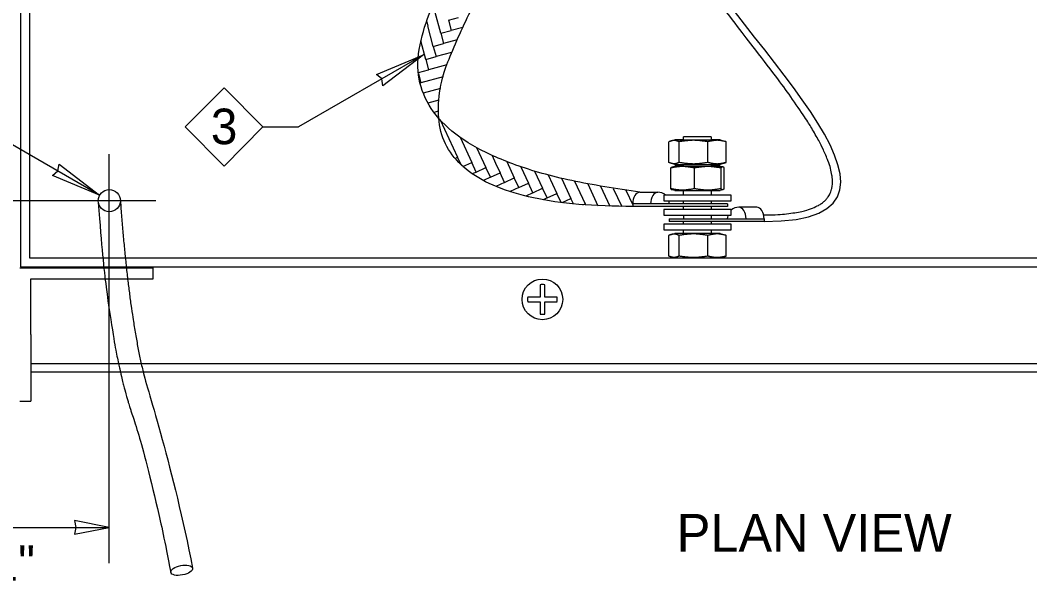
# Model space of a CAD drawing. Extents: x 99862 to 103680, y 99470 to 102076.
# Drawn here: x 101295.5 to 101750, y 101268.9 to 101521 of the extents above; entities that cross this region are included whole.
import ezdxf

# ---------------------------------------------------------------- set-up
doc = ezdxf.new("R2010")
doc.units = 0
for name, color, linetype in [('Level 1', 7, 'Continuous'), ('Level 10', 7, 'Continuous'), ('Level 11', 7, 'Continuous'), ('Level 13', 7, 'Continuous'), ('Level 14', 7, 'Continuous'), ('Level 15', 7, 'Continuous'), ('Level 20', 7, 'Continuous'), ('Level 6', 7, 'Continuous'), ('Level 9', 7, 'Continuous')]:
    doc.layers.add(name, color=color, linetype=linetype)

msp = doc.modelspace()

# ---------------------------------------------------------------- linework, layer by layer
at = {"layer": 'Level 1'}
for p, q in [((101295.71, 101675.72), (101295.71, 101410.08)), ((101299.71, 101675.72), (101299.71, 101414.08)), ((101295.71, 101410.08), (102014.99, 101410.08)), ((101299.71, 101414.08), (102010.99, 101414.08)), ((102010.35, 101366.5), (101300.35, 101366.5)), ((101300.35, 101362.86), (102010.35, 101362.86))]:
    msp.add_line(p, q, dxfattribs=at)
msp.add_circle((101335.63, 101439.83), 5, dxfattribs=at)
at = {"layer": 'Level 10'}
for p, q in [((101587.44, 101457.01), (101587.44, 101466.35)), ((101588.22, 101466.61), (101590.23, 101467.17)), ((101592.13, 101457.01), (101592.13, 101466.35)), ((101594.13, 101467.17), (101594.13, 101468.51)), ((101605.06, 101457.01), (101605.06, 101466.35)), ((101606.63, 101468.51), (101606.63, 101467.17)), ((101610.54, 101467.17), (101612.55, 101466.61)), ((101612.54, 101466.61), (101613.32, 101466.35)), ((101613.32, 101457.01), (101613.32, 101466.35)), ((101590.23, 101456.19), (101588.22, 101456.75)), ((101588.96, 101455.03), (101590.23, 101455.38)), ((101594.13, 101455.38), (101594.13, 101456.19)), ((101606.63, 101456.19), (101606.63, 101455.38)), ((101612.55, 101456.75), (101610.54, 101456.19)), ((101610.54, 101455.38), (101611.8, 101455.03)), ((101612.54, 101456.75), (101613.32, 101457.01)), ((101588.43, 101454.56), (101588.98, 101455.03)), ((101588.43, 101445.23), (101588.43, 101454.56)), ((101599.05, 101445.23), (101599.05, 101454.56)), ((101611, 101445.22), (101611.01, 101454.56)), ((101612.34, 101454.56), (101611.79, 101455.03)), ((101612.34, 101445.22), (101612.34, 101454.56)), ((101588.43, 101445.23), (101588.97, 101444.75)), ((101590.22, 101444.41), (101588.96, 101444.76)), ((101594.13, 101442.33), (101594.13, 101444.41)), ((101606.63, 101444.41), (101606.63, 101442.33)), ((101611.8, 101444.76), (101610.54, 101444.41)), ((101612.34, 101445.22), (101611.79, 101444.75)), ((101594.13, 101438.46), (101594.13, 101439.83)), ((101594.13, 101435.91), (101594.13, 101437.21)), ((101606.63, 101439.83), (101606.63, 101438.46)), ((101606.63, 101437.21), (101606.63, 101435.91)), ((101594.13, 101433.41), (101594.13, 101431.73)), ((101606.63, 101433.41), (101606.63, 101431.73)), ((101594.13, 101429.23), (101594.13, 101430.48)), ((101606.63, 101430.48), (101606.63, 101429.23)), ((101587.44, 101414.91), (101587.44, 101424.24)), ((101588.22, 101424.5), (101590.22, 101425.06)), ((101592.12, 101414.9), (101592.12, 101424.24)), ((101594.13, 101425.06), (101594.13, 101426.73)), ((101605.06, 101414.9), (101605.06, 101424.24)), ((101606.63, 101426.73), (101606.63, 101425.06)), ((101610.54, 101425.06), (101612.55, 101424.5)), ((101612.53, 101424.5), (101613.32, 101424.24)), ((101613.32, 101414.9), (101613.32, 101424.24)), ((101590.22, 101414.09), (101588.22, 101414.64)), ((101612.55, 101414.65), (101610.54, 101414.08)), ((101612.53, 101414.64), (101613.32, 101414.9)), ((101529.56, 101402.06), (101529.56, 101396.49)), ((101531.62, 101396.49), (101531.62, 101402.06)), ((101529.56, 101396.49), (101523.99, 101396.49)), ((101537.19, 101396.49), (101531.62, 101396.49)), ((101523.99, 101394.42), (101529.56, 101394.42)), ((101529.56, 101394.42), (101529.56, 101388.86)), ((101531.62, 101388.86), (101531.62, 101394.42)), ((101531.62, 101394.42), (101537.19, 101394.42))]:
    msp.add_line(p, q, dxfattribs=at)
msp.add_circle((101530.59, 101395.46), 9.15, dxfattribs=at)
for centre, start, end in [((101530.59, 101393.46), 83.1584, 96.8416), ((101532.59, 101395.46), 173.1584, 186.8416), ((101528.59, 101395.46), 353.1584, 6.8416), ((101530.59, 101397.46), 263.1584, 276.8416)]:
    msp.add_arc(centre, 8.66, start, end, dxfattribs=at)
for centre, major_axis, start_param, end_param in [((101600.38, 101467.17), (10.16, 0), 2.233649, 3.141532), ((101600.38, 101467.17), (10.16, 0), 3.141532, 5.077835), ((101600.38, 101468.51), (-6.25, 0), 3.141588, 6.283185), ((101600.38, 101467.17), (-6.25, 0), 6.263057, 6.283185), ((101600.38, 101467.17), (-6.25, 0), 0, 3.141593), ((101600.38, 101467.17), (10.16, 0), 5.077835, 6.283246), ((101600.38, 101467.17), (10.16, 0), 0.00006, 0.907905), ((101600.38, 101467.17), (-6.25, 0), 3.141593, 3.160019), ((101600.38, 101456.19), (10.16, 0), 3.141653, 5.077835), ((101600.38, 101455.38), (10.16, 0), 2.233603, 3.141532), ((101600.38, 101455.38), (10.16, 0), 3.141532, 5.657889), ((101600.38, 101456.19), (-6.25, 0), 6.276167, 6.283185), ((101600.38, 101455.38), (-6.25, 0), 6.270079, 6.283185), ((101600.38, 101455.38), (-6.25, 0), 6.283185, 9.424778), ((101600.38, 101456.19), (10.16, 0), 5.077835, 6.283125), ((101600.38, 101455.38), (10.16, 0), 0.00006, 0.907855), ((101600.38, 101455.38), (10.16, 0), 5.657889, 6.283246), ((101600.38, 101444.41), (10.16, 0), 3.141653, 5.657889), ((101600.38, 101444.41), (-6.25, 0), 6.270079, 6.283185), ((101600.38, 101444.41), (10.16, 0), 5.657889, 6.283125), ((101600.38, 101425.06), (10.16, 0), 0.00006, 3.141524)]:
    msp.add_ellipse(centre, major_axis=major_axis, ratio=0.000017, start_param=start_param, end_param=end_param, dxfattribs=at)
for points in [[(101588.23, 101466.62), (101587.97, 101466.53), (101587.71, 101466.44), (101587.44, 101466.35)], [(101592.13, 101466.35), (101590.83, 101466.87), (101589.53, 101467.02), (101588.23, 101466.62)], [(101605.06, 101466.35), (101600.75, 101467.02), (101596.44, 101467.01), (101592.13, 101466.35)], [(101613.32, 101466.35), (101610.57, 101467.02), (101607.82, 101467), (101605.06, 101466.35)], [(101588.23, 101456.75), (101587.97, 101456.84), (101587.71, 101456.93), (101587.44, 101457.01)], [(101592.13, 101457.01), (101590.83, 101456.5), (101589.53, 101456.34), (101588.23, 101456.75)], [(101599.05, 101454.56), (101595.53, 101455.18), (101591.95, 101455.25), (101588.43, 101454.56)], [(101605.06, 101457.01), (101600.75, 101456.34), (101596.44, 101456.36), (101592.13, 101457.01)], [(101611.01, 101454.56), (101607.02, 101455.23), (101603.04, 101455.22), (101599.05, 101454.56)], [(101613.32, 101457.01), (101610.57, 101456.34), (101607.82, 101456.36), (101605.06, 101457.01)], [(101611.79, 101455.03), (101611.53, 101455.14), (101611.27, 101454.85), (101611.01, 101454.56)], [(101599.05, 101445.23), (101595.53, 101444.6), (101591.95, 101444.53), (101588.43, 101445.23)], [(101611, 101445.22), (101607.02, 101444.55), (101603.04, 101444.57), (101599.05, 101445.23)], [(101611.79, 101444.75), (101611.53, 101444.65), (101611.27, 101444.94), (101611, 101445.22)], [(101588.23, 101424.51), (101587.97, 101424.42), (101587.7, 101424.33), (101587.44, 101424.24)], [(101592.12, 101424.24), (101590.83, 101424.76), (101589.53, 101424.91), (101588.23, 101424.51)], [(101605.06, 101424.24), (101600.75, 101424.91), (101596.44, 101424.9), (101592.12, 101424.24)], [(101613.32, 101424.24), (101610.57, 101424.91), (101607.82, 101424.9), (101605.06, 101424.24)], [(101588.23, 101414.64), (101587.97, 101414.73), (101587.7, 101414.82), (101587.44, 101414.91)], [(101592.12, 101414.9), (101590.83, 101414.39), (101589.53, 101414.23), (101588.23, 101414.64)], [(101605.06, 101414.9), (101600.75, 101414.23), (101596.44, 101414.25), (101592.12, 101414.9)], [(101613.32, 101414.9), (101610.57, 101414.23), (101607.82, 101414.25), (101605.06, 101414.9)]]:
    msp.add_open_spline(points, degree=2, dxfattribs=at)
at = {"layer": 'Level 11'}
for p, q in [((101484.87, 101515.16), (101482.39, 101524.43)), ((101478.5, 101520.38), (101478.99, 101518.55)), ((101488.27, 101521.04), (101492.9, 101522.28)), ((101488.27, 101521.04), (101489.51, 101516.4)), ((101481.48, 101509.28), (101478.99, 101518.55)), ((101484.87, 101515.16), (101489.51, 101516.4)), ((101484.87, 101515.16), (101486.11, 101510.52)), ((101494.76, 101517.81), (101489.51, 101516.4)), ((101478.08, 101503.4), (101475.83, 101511.8)), ((101481.48, 101509.28), (101486.11, 101510.52)), ((101492.19, 101512.15), (101486.11, 101510.52)), ((101481.48, 101509.28), (101482.72, 101504.64)), ((101489.73, 101506.52), (101482.72, 101504.64)), ((101478.08, 101503.4), (101482.72, 101504.64)), ((101478.08, 101503.4), (101479.32, 101498.77)), ((101487.61, 101500.99), (101479.32, 101498.77)), ((101474.75, 101497.54), (101479.33, 101498.77)), ((101474.79, 101497.13), (101475.93, 101492.89)), ((101475.54, 101492.78), (101475.93, 101492.89)), ((101485.89, 101495.55), (101475.93, 101492.89)), ((101484.65, 101490.25), (101476.98, 101488.2)), ((101483.91, 101485.09), (101479.06, 101483.79)), ((101483.7, 101480.06), (101481.8, 101479.55)), ((101484.59, 101476.19), (101492.42, 101459.4)), ((101493.53, 101468.37), (101498.8, 101457.07)), ((101500.99, 101463.72), (101505.18, 101454.75)), ((101507.91, 101460.25), (101509.53, 101456.78)), ((101491.29, 101458.87), (101492.42, 101459.4)), ((101494.02, 101455.97), (101492.42, 101459.4)), ((101494.83, 101455.22), (101498.8, 101457.07)), ((101500.83, 101452.72), (101498.8, 101457.07)), ((101509.53, 101456.78), (101511.55, 101452.43)), ((101514.51, 101457.46), (101517.93, 101450.11)), ((101520.88, 101455.15), (101524.31, 101447.79)), ((101500.83, 101452.72), (101499.06, 101451.9)), ((101500.83, 101452.72), (101505.18, 101454.75)), ((101507.2, 101450.4), (101505.18, 101454.75)), ((101507.2, 101450.4), (101511.55, 101452.43)), ((101513.58, 101448.08), (101511.55, 101452.43)), ((101527.1, 101453.16), (101530.69, 101445.47)), ((101533.19, 101451.47), (101537.07, 101443.14)), ((101507.2, 101450.4), (101504.01, 101448.91)), ((101507.2, 101450.4), (101507.2, 101450.4)), ((101513.58, 101448.08), (101509.66, 101446.25)), ((101513.58, 101448.08), (101517.93, 101450.11)), ((101519.96, 101445.76), (101517.93, 101450.11)), ((101519.96, 101445.76), (101524.31, 101447.79)), ((101526.34, 101443.44), (101524.31, 101447.79)), ((101539.19, 101449.95), (101543.45, 101440.82)), ((101545.11, 101448.61), (101549.83, 101438.5)), ((101550.97, 101447.4), (101555.54, 101437.6)), ((101556.76, 101446.34), (101560.94, 101437.37)), ((101519.96, 101445.76), (101516.01, 101443.92)), ((101526.34, 101443.44), (101523.1, 101441.93)), ((101526.34, 101443.44), (101530.69, 101445.47)), ((101532.72, 101441.12), (101530.69, 101445.47)), ((101532.72, 101441.12), (101537.07, 101443.14)), ((101538.98, 101439.05), (101537.07, 101443.14)), ((101562.5, 101445.39), (101566.3, 101437.25)), ((101568.2, 101444.53), (101571.25, 101437.99)), ((101532.72, 101441.12), (101530.93, 101440.28)), ((101539.51, 101438.99), (101543.45, 101440.82)), ((101544.57, 101438.43), (101543.45, 101440.82)), ((101548.85, 101438.04), (101549.83, 101438.5)), ((101550.08, 101437.95), (101549.83, 101438.5))]:
    msp.add_line(p, q, dxfattribs=at)
for points in [[(101574.51, 101443.65), (101428.47, 101462.51), (101563.15, 101636.34), (101684.52, 101785.6), (101556.08, 101806.12), (101516.64, 101714.68), (101504.48, 101712.39)], [(101571.25, 101437.21), (101460.29, 101437.21), (101519.62, 101576.95), (101643.97, 101690.88), (101661.74, 101764.81), (101582.83, 101796.17), (101529.92, 101740.64), (101501.22, 101722.24)]]:
    msp.add_open_spline(points, degree=2, dxfattribs=at)
at = {"layer": 'Level 13'}
for p, q in [((101574.51, 101443.65), (101582.57, 101443.65)), ((101571.25, 101438.46), (101571.25, 101437.21)), ((101613.87, 101438.46), (101571.25, 101438.46)), ((101613.87, 101437.21), (101571.25, 101437.21)), ((101613.87, 101438.46), (101613.87, 101437.21)), ((101627.09, 101436.91), (101619.02, 101436.91)), ((101587.73, 101431.73), (101587.73, 101430.48)), ((101587.73, 101431.73), (101630.35, 101431.73)), ((101630.35, 101430.48), (101587.73, 101430.48)), ((101630.35, 101431.73), (101630.35, 101430.48))]:
    msp.add_line(p, q, dxfattribs=at)
for points in [[(101585.28, 101439.83), (101615.49, 101439.83), (101615.49, 101442.33), (101585.28, 101442.33)], [(101585.28, 101433.41), (101615.49, 101433.41), (101615.49, 101435.91), (101585.28, 101435.91)], [(101585.27, 101426.73), (101615.49, 101426.73), (101615.49, 101429.23), (101585.27, 101429.23)]]:
    msp.add_lwpolyline(points, close=True, dxfattribs=at)
for centre, start, end in [((101582.57, 101438.46), 48.2543, 90.0019), ((101582.57, 101438.46), 0.0024, 15.3086), ((101619.02, 101431.73), 89.9981, 131.7457), ((101619.02, 101431.73), 164.6914, 179.9976)]:
    msp.add_arc(centre, 5.19, start, end, dxfattribs=at)
for centre, major_axis, ratio, start_param, end_param in [((101574.51, 101438.46), (0, 5.19), 0.628956, 6.283185, 7.853993), ((101582.57, 101438.46), (0, -5.19), 0.628956, 3.141593, 4.7124), ((101600.38, 101442.33), (-6.4, 0), 0.000017, 3.141593, 3.359984), ((101619.02, 101431.73), (0, -5.19), 0.628956, 1.570785, 3.141593), ((101627.09, 101431.73), (0, 5.19), 0.628956, 4.712377, 6.283185)]:
    msp.add_ellipse(centre, major_axis=major_axis, ratio=ratio, start_param=start_param, end_param=end_param, dxfattribs=at)
at = {"layer": 'Level 14'}
msp.add_ellipse((101368.2, 101273.59), major_axis=(4.9, 0.94), ratio=0.429494, dxfattribs=at)
for points, degree in [([(101330.68, 101439.11), (101332.16, 101418.41), (101334.1, 101400.31), (101337.72, 101376.97), (101339.05, 101369.82), (101340.55, 101363.15), (101340.58, 101363.01), (101340.61, 101362.87)], 3), ([(101340.63, 101439.83), (101344.08, 101391.56), (101350.84, 101362.89)], 2), ([(101340.61, 101362.87), (101341.31, 101359.76), (101342.05, 101356.79), (101343.21, 101352.48), (101343.62, 101351.03), (101344.25, 101348.93), (101344.57, 101347.89), (101344.94, 101346.7), (101345.13, 101346.11), (101345.23, 101345.81), (101345.27, 101345.69), (101345.3, 101345.61), (101345.31, 101345.56), (101348.49, 101335.92), (101351.58, 101325.03), (101357.58, 101300.73), (101360.49, 101287.31), (101363.3, 101272.65)], 3), ([(101350.85, 101362.88), (101352.7, 101355.02), (101364.57, 101318.96), (101373.1, 101274.53)], 3)]:
    msp.add_open_spline(points, degree=degree, dxfattribs=at)
at = {"layer": 'Level 15'}
for p, q in [((101477.12, 101505.5), (101420.82, 101473)), ((101331.3, 101442.33), (101223.04, 101504.83)), ((101404.82, 101473), (101420.82, 101473)), ((101335.63, 101276.86), (101335.63, 101460.83)), ((101356.63, 101439.83), (101162.49, 101439.83)), ((101248.49, 101292.86), (101335.63, 101292.86))]:
    msp.add_line(p, q, dxfattribs=at)
for points in [[(101477.12, 101505.5), (101458.84, 101491.5), (101458.26, 101494.61), (101455.85, 101496.67)], [(101331.3, 101442.33), (101310.03, 101451.16), (101312.44, 101453.21), (101313.02, 101456.33)], [(101335.63, 101292.86), (101319.9, 101295.95), (101320.63, 101292.86), (101319.9, 101289.78)]]:
    msp.add_lwpolyline(points, close=True, dxfattribs=at)
at = {"layer": 'Level 20'}
msp.add_lwpolyline([(101387.27, 101455.45), (101404.82, 101473), (101387.27, 101490.55), (101369.72, 101473)], close=True, dxfattribs=at)
at = {"layer": 'Level 6'}
for p, q in [((101295.35, 101409.72), (101355.35, 101409.72)), ((101355.35, 101404.72), (101355.35, 101409.72)), ((101300.35, 101379.72), (101300.35, 101404.72)), ((101300.35, 101404.72), (101355.35, 101404.72)), ((101300.35, 101379.72), (101300.35, 101349.72)), ((101295.35, 101349.72), (101300.35, 101349.72))]:
    msp.add_line(p, q, dxfattribs=at)
at = {"layer": 'Level 9'}
for points in [[(101630.35, 101430.48), (101719.34, 101430.48), (101502.28, 101601.88), (101631.54, 101641.46), (101702.27, 101640.37)], [(101630.35, 101433.48), (101635.79, 101433.48), (101640.41, 101433.82), (101648.11, 101435.08), (101651.19, 101436), (101654.76, 101437.68), (101655.77, 101438.28), (101657.48, 101439.56), (101658.18, 101440.23), (101659.34, 101441.65), (101659.8, 101442.38), (101660.51, 101443.97), (101660.77, 101444.82), (101661.1, 101446.66), (101661.18, 101447.66), (101661.12, 101449.81), (101660.99, 101450.96), (101660.29, 101454.62), (101659.42, 101457.35), (101656.94, 101463.21), (101655.35, 101466.35), (101651.56, 101472.94), (101649.38, 101476.39), (101642.17, 101487.11), (101636.49, 101494.71), (101624.55, 101510.32), (101618.29, 101518.33), (101606.35, 101534.25), (101600.66, 101542.17), (101593.42, 101553.66), (101591.22, 101557.42), (101587.39, 101564.78), (101585.76, 101568.37), (101583.23, 101575.37), (101582.33, 101578.75), (101581.26, 101585.28), (101581.08, 101588.44), (101581.43, 101594.5), (101581.95, 101597.41), (101583.65, 101602.95), (101584.83, 101605.58), (101587.77, 101610.54), (101589.53, 101612.86), (101593.57, 101617.21), (101595.84, 101619.24), (101603.34, 101624.9), (101609.24, 101628.11), (101622.48, 101633.57), (101629.82, 101635.81), (101645.62, 101639.41), (101654.08, 101640.76), (101675.42, 101643.05), (101688.69, 101643.58), (101702.27, 101643.37)]]:
    msp.add_open_spline(points, degree=3, dxfattribs=at)

# ---------------------------------------------------------------- texts
at = {"layer": 'Level 20'}
for s, height, p in [('3', 16, (101381.37, 101465.26)), ('PLAN VIEW', 17, (101591.04, 101281.92)), ('1"', 16, (101282.69, 101268.86))]:
    msp.add_text(s, height=height, dxfattribs=at).set_placement(p)

doc.saveas('drawing.dxf')
